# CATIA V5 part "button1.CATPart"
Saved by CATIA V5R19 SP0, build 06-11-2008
Part number: button1
Bounding box of the stored display mesh (mm): x -52.07 to -49.53, y -12.55 to -4.541, z -3.877 to -2.219
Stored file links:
  F:\CAD\ipod\button1.CATPart
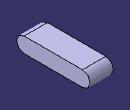
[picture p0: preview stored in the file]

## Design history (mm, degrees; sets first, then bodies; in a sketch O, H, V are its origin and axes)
Body1 (main body)
  DatumSurface1
  DatumCurve1
  DatumCurve2
  Sketch1 on face of DatumSurface1, origin (-49.53, 0, 0), H (0, -1, 0), V (0, 0, 1)
    construction line L1 (5.3703, -3.048) -> (11.7203, -3.048)
    line L2 (5.3703, -2.2187) -> (11.7203, -2.2187)
    line L3 (11.7203, -3.8773) -> (5.3703, -3.8773)
    arc A1 centre (11.7203, -3.048) radius 0.8293 from (11.7203, -2.2187) to (11.7203, -3.8773) cw
    arc A2 centre (5.3703, -3.048) radius 0.8293 from (5.3703, -3.8773) to (5.3703, -2.2187) cw
    reference projected line E1 (19.4895, -2.0917) -> (4.2495, -2.0917) from edge of DatumCurve1
    reference projected line E2 (4.2495, -4.0043) -> (19.4895, -4.0043) from edge of DatumCurve2
    distance L2 E1 = 0.127
    distance L3 E2 = 0.127
    length L2 = 6.35
    horizontal: L1 H
    tangency: A1 L2, A2 L2, A1 L3, A2 L3
  Pad1: profile Sketch1, direction (-1, 0, 0), length 2.54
